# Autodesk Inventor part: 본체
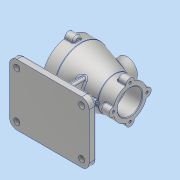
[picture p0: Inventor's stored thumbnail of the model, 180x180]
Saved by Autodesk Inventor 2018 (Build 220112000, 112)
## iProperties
Created: 2020-12
Part Number: 본체
Material: 알루미늄 6061
Document SubType Name: Modeling
Designer: home
Density: 2.7 g/cm^3
Appearance: 알루미늄 - 평지
Mass: 1030.13 g
Surface Area: 850.653 cm^2
Volume: 381.528 cm^3
Author: home
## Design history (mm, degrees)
sketch "스케치1"
  geometry: L1 (53, -50)-(-53, -50); L2 (-65, -38)-(-65, 38); L3 (-53, 50)-(53, 50); L4 (65, 38)-(65, -38); C1 r 5 at (53, -38); C2 r 5 at (53, 38); C3 r 5 at (-53, 38); C4 r 5 at (-53, -38); A1 r 12 centre (53, -38) between (53, -50) and (65, -38); A2 r 12 centre (53, 38) between (65, 38) and (53, 50); A3 r 12 centre (-53, 38) between (-53, 50) and (-65, 38); A4 r 12 centre (-53, -38) between (-65, -38) and (-53, -50); 4 further points
  constraints: 8 centre point, 8 end point, 8 point on circle, 8 tangent, 6 point on line, 4 coincident, 3 equal radius, 2 parallel, 1 horizontal, 1 perpendicular
  dimensions: "d0" = 130 distance of point (65, -50) point (-65, -50); "d1" = 100 distance of point (-65, -50) point (-65, 50); "d2" = 65 distance from line of L2 point (0, 0); "d3" = 50 distance from line of point (0, 0) L1; "d4" = 12 radius of A1; "d5" = 10 diameter of C1; "d6" = 10 diameter of C2; "d7" = 10 diameter of C3; "d8" = 10 diameter of C4
extrude "돌출1" new body sketch "스케치1" distance "d9" = 12; taper "d10" = 0 deg
sketch "스케치2"
  geometry: L1 (-70.943, 82)-(67.415, 82); L2 (58, 0)-(48, 0) reference; L3 (50, 103)-(50, 109.5); L4 (50, 109.5)-(25.44, 109.5); L5 (24.578, 109.627)-(-29.578, 125.873); L6 (-30.44, 126)-(-50, 126); L7 (-50, 126)-(-50, 115); L8 (-27, 104.161)-(-27, 108); L9 (-24, 108)-(17, 108); L10 (23, 102)-(49, 102); L11 (-49, 114)-(-30, 114); L12 (-27, 111)-(-27, 111); L13 (20, 105)-(20, 105); L14 (-49, 114)-(-50, 115); L15 (49, 102)-(50, 103); A1 r 3 centre (-30, 111) between (-27, 111) and (-30, 114); A2 r 3 centre (-24, 111) between (-27, 111) and (-24, 108); A3 r 3 centre (17, 105) between (20, 105) and (17, 108); A4 r 3 centre (23, 105) between (20, 105) and (23, 102); A5 r 3 centre (-30.44, 123) between (-29.578, 125.873) and (-30.44, 126); A6 r 3 centre (25.44, 112.5) between (24.578, 109.627) and (25.44, 109.5); 7 further points
  constraints: 28 end point, 14 point on line, 12 point on circle, 12 tangent, 6 centre point, 6 perpendicular, 3 equal radius, 2 vertical, 1 horizontal, 1 parallel
  dimensions: "d11" = 82 distance between parallel lines of L2 L1; "d12" = 88 diameter of L6 L1; "d13" = 55 diameter of L4 L1; "d14" = 20 distance of point (-30, 126) L6.end; "d15" = 100 distance between parallel lines of L3 L7; "d16" = 50 horizontal distance of point (0, 0) L6.end; "d18" = 47 distance of L8.end point (20, 108); "d19" = 23 distance of point (-50, 114) point (-27, 114); "d20" = 64 diameter of L11 L1; "d21" = 52 diameter of L9 L1; "d22" = 40 diameter of L10 L1; "d23" = 3 radius of A1; "d24" = 3 radius of A3 (derived); "d25" = 25 distance of L3.end point (25, 109.5); "d26" = 3 radius of A5 (derived); "d27" = 1 distance of L11.start point (-50, 114); "d28" = 1 distance of L7.end point (-50, 114) (= d27); "d29" = 1 distance of L10.end point (50, 102) (= d27); "d30" = 1 distance of L3.start point (50, 102) (= d29)
revolve "회전1" sketch "스케치2" stored, may be unused: angle "d31" = 90 deg
sketch "스케치5"
  geometry: A1 r 7 centre (0, 27.5) between (6.943, 26.609) and (-6.943, 26.609); A2 r 27.5 centre (0, 0) between (6.943, 26.609) and (-6.943, 26.609); 2 further points
  constraints: 5 point on circle, 2 centre point, 2 vertical alignment, 1 coincident, 1 other
  dimensions: "d47" = 14 diameter of A1
extrude "돌출3" join sketch "스케치5" distance "d48" = 15; taper "d49" = 0 deg
fillet "모깎기3" dims "d57" = 3
fillet "모깎기4" dims "d58" = 1
sketch "스케치7"
  geometry: L1 (-29.578, 38.127)-(24.578, 54.373) reference; L2 (53, 12)-(-53, 12) reference; L3 (-24, 12)-(-24, 39.8); 1 further point
  constraints: 2 end point, 2 point on line, 1 vertical
  dimensions: "d62" = 24 distance from line of point (0, 0) L3
feature "리브1" sketch "스케치7" dims "d63" = 1, "d64" = 8, "d65" = 0, "d66" = 0, "d67" = 1, "d68" = 1
sketch "스케치8"
  geometry: L1 (-29.578, 38.127)-(24.578, 54.373) reference; L2 (53, 12)-(-53, 12) reference; L3 (24, 12)-(24, 54.2); 1 further point
  constraints: 2 end point, 2 point on line, 1 vertical
  dimensions: "d69" = 24 distance from line of point (0, 0) L3
feature "리브2" sketch "스케치8" dims "d70" = 1, "d71" = 8, "d72" = 0, "d73" = 0, "d74" = 1, "d75" = 1
sketch "스케치9"
  geometry: L1 (0, 38)-(0, -38) reference; L2 (0, 38)-(12, 38) reference; L3 (12, -38)-(12, 38) reference; L4 (0, -38)-(12, -38) reference; L5 (12, -38)-(12, 38) reference; L6 (12, 25)-(67.303, 25); L7 (12, -25)-(67.303, -25); A1 r 29 centre (82, 0) between (67.303, 25) and (67.303, -25) reference; 1 further point
  constraints: 4 end point, 2 point on circle, 2 point on line, 1 parallel, 1 perpendicular
  dimensions: "d76" = 50 distance between parallel lines of L6 L7; "d77" = 25 distance from line of point (0, 0) L7
feature "리브3" sketch "스케치9" dims "d78" = 1, "d79" = 8, "d80" = 0, "d81" = 0, "d82" = 1, "d83" = 1
fillet "모깎기5" dims "d84" = 3
node "작업 평면1"
sketch "스케치10"
  geometry: C1 r 17 at (0, 0); 1 further point
  constraints: 1 centre point, 1 coincident
  dimensions: "d87" = 34 diameter of C1
extrude "돌출4" join sketch "스케치10" stored distance "d88" = 15; taper "d89" = 0 deg
sketch "스케치11"
  geometry: 2 further points
  constraints: 1 coincident
hole "구멍3" sketch "스케치11" at (0, 0) diameter "d90" = 22; stored, may be unused: countersink angle "d94" = 90 deg, drill point angle "d96" = 0 deg; dims "d91" = 10, "d92" = 28, "d93" = 1, "d95" = 30
chamfer "모따기1" distance "d97" = 1; stored, may be unused: second distance "d98" = 2, angle "d99" = 45 deg
sketch "스케치12"
  geometry: L1 (-53, -50)-(53, -50) reference; 2 further points
  constraints: 1 vertical alignment, 1 other
  dimensions: "d100" = 10 distance from line of L1 point (0, -40)
feature "엠보싱1" sketch "스케치12" dims "d0" = 130, "d1" = 100, "d2" = 65, "d3" = 50, "d4" = 12, "d5" = 10, "d6" = 10, "d7" = 10, "d8" = 10, "d101" = 0.5, "d102" = 0
fillet "모깎기7" dims "d103" = 3
fillet "모깎기8" dims "d104" = 3
sketch "스케치13"
  geometry: A1 r 7 centre (0, 44) between (6.978, 43.443) and (-6.978, 43.443); A2 r 44 centre (0, 0) between (-6.978, 43.443) and (6.978, 43.443) reference; 1 further point
  constraints: 4 point on circle, 1 centre point
  dimensions: "d105" = 14 diameter of A1; "d106" = 44 distance of A2.centre A1.centre
extrude "돌출5" join sketch "스케치13" distance "d107" = 15; taper "d108" = 0 deg
fillet "모깎기9" dims "d109" = 3
fillet "모깎기10" dims "d110" = 1
sketch "스케치14"
  geometry: A1 r 7 centre (0, 0) between (6.996, 0.249) and (-6.996, 0.249) reference; 2 further points
  constraints: 1 coincident
hole "구멍4" sketch "스케치14" at (0, 0) diameter "d111" = 4.134; stored, may be unused: countersink angle "d115" = 90 deg, drill point angle "d117" = 118 deg; dims "d112" = 9, "d113" = 28, "d114" = 1, "d116" = 11
fillet "모깎기11" dims "d121" = 1
sketch "스케치15"
  geometry: C1 r 20 at (0, -27.5) reference; 2 further points
  constraints: 1 vertical alignment
  dimensions: "d122" = 27.5 distance of C1.centre point (0, 0)
hole "구멍5" sketch "스케치15" at (0, 0) diameter "d123" = 4.134; stored, may be unused: countersink angle "d127" = 90 deg, drill point angle "d129" = 118 deg; dims "d124" = 9, "d125" = 28, "d126" = 1, "d128" = 11
node "솔리드1"
pattern_circular "원형 패턴2" dims angle "d60" = 360 deg
mirror "미러1"
pattern_circular "원형 패턴3" dims "d119" = 360 deg
pattern_circular "원형 패턴4" dims angle "d131" = 360 deg
node "투영된 루프1"
feature "耀䀒"
other parameters: "d86" = 127
